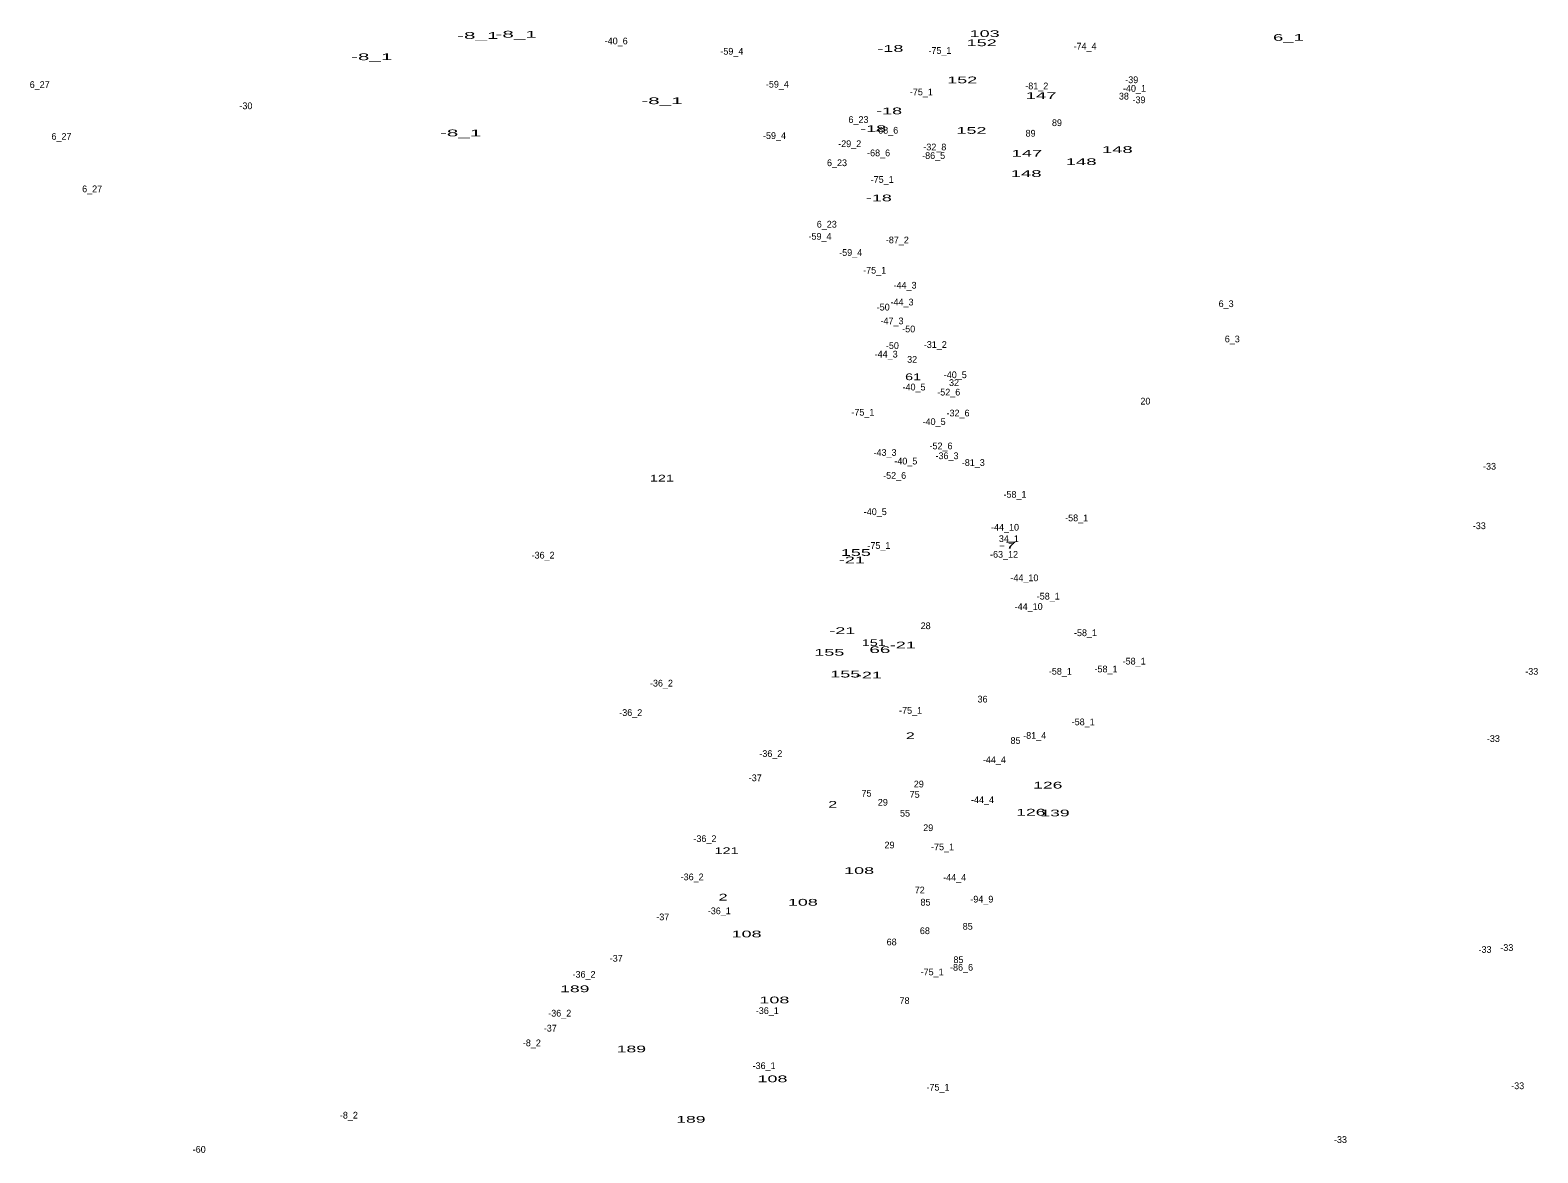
# Model space of a CAD drawing. Extents: x -659624 to -656248, y -1006345 to -1003555.
# Drawn here: x -658623 to -657726, y -1005682 to -1005014 of the extents above; entities that cross this region are included whole.
import ezdxf
from ezdxf.enums import TextEntityAlignment as Align

# ---------------------------------------------------------------- set-up
doc = ezdxf.new("R2010")
doc.units = 0
doc.header["$LTSCALE"] = 1.6
doc.layers.add('24', color=7, linetype='Continuous')

msp = doc.modelspace()

# ---------------------------------------------------------------- texts
at = {"layer": '24'}
for s, width, p in [('-8_1', 2.3, (-658356.751, -1005019.29)), ('-8_1', 2.3, (-658333.941, -1005018.53)), ('103', 2, (-658055.354, -1005018.16)), ('-18', 2, (-658111.421, -1005027.01)), ('152', 2, (-658057.107, -1005023.62)), ('6_1', 2.05, (-657874.723, -1005020.45)), ('-8_1', 2.3, (-658419.801, -1005031.94)), ('152', 2, (-658068.707, -1005045.69)), ('147', 2.05, (-658021.768, -1005054.98)), ('-8_1', 2.3, (-658247.211, -1005058.1)), ('-18', 2, (-658112.181, -1005064.11)), ('-8_1', 2.3, (-658366.931, -1005077.22)), ('-18', 2, (-658121.631, -1005074.67)), ('152', 2, (-658063.197, -1005075.75)), ('147', 2.05, (-658030.228, -1005089.32)), ('148', 2.05, (-657976.473, -1005087.09)), ('148', 2.05, (-657997.963, -1005094.32)), ('148', 2.05, (-658030.673, -1005101.36)), ('-18', 2, (-658118.271, -1005115.86)), ('61', 1.6, (-658097.913, -1005222.23)), ('121', 1.6, (-658247.274, -1005282.51)), ('-7', 2.2, (-658041.779, -1005322.36)), ('-21', 2, (-658134.281, -1005331.12)), ('155', 2, (-658131.937, -1005326.72)), ('-21', 2, (-658139.981, -1005373.17)), ('155', 2, (-658147.717, -1005386.08)), ('151', 1.6, (-658121.274, -1005380.35)), ('66', 2.1, (-658117.661, -1005384.48)), ('-21', 2, (-658104.041, -1005381.73)), ('155', 2, (-658138.217, -1005399.02)), ('-21', 2, (-658124.191, -1005399.61)), ('2', 1.8, (-658099.571, -1005435.69)), ('126', 1.95, (-658017.813, -1005465.05)), ('2', 1.8, (-658145.701, -1005476.46)), ('126', 1.95, (-658027.893, -1005481.13)), ('139', 1.95, (-658013.553, -1005481.58)), ('121', 1.6, (-658208.824, -1005504.04)), ('108', 2, (-658130.014, -1005515.85)), ('2', 1.8, (-658210.871, -1005531.65)), ('108', 2, (-658163.464, -1005534.69)), ('108', 2, (-658196.914, -1005553.54)), ('189', 1.95, (-658299.063, -1005586.15)), ('108', 2, (-658180.384, -1005592.77)), ('189', 1.95, (-658265.403, -1005621.92)), ('108', 2, (-658181.534, -1005639.69)), ('189', 1.95, (-658230.033, -1005663.77))]:
    msp.add_text(s, height=4, dxfattribs=dict(at, width=width)).set_placement(p, align=Align.CENTER)
for s, p in [('-40_6', (-658274.456, -1005022.54)), ('-59_4', (-658205.662, -1005028.67)), ('-75_1', (-658081.942, -1005028.19)), ('-74_4', (-657995.636, -1005025.64)), ('-39', (-657967.9, -1005045.62)), ('6_27', (-658617.226, -1005048.46)), ('-59_4', (-658178.592, -1005048.26)), ('-75_1', (-658093.002, -1005052.85)), ('-81_2', (-658024.366, -1005049.28)), ('38', (-657972.557, -1005055.35)), ('-40_1', (-657966.274, -1005050.72)), ('-30', (-658494.619, -1005061.09)), ('-39', (-657963.58, -1005057.54)), ('6_23', (-658130.39, -1005069.28)), ('89', (-658012.373, -1005071.15)), ('6_27', (-658604.296, -1005079.28)), ('-59_4', (-658180.322, -1005078.8)), ('-68_6', (-658113.613, -1005075.63)), ('89', (-658028.043, -1005077.4)), ('-29_2', (-658135.598, -1005083.66)), ('-68_6', (-658118.413, -1005089.08)), ('-86_5', (-658085.688, -1005090.67)), ('-32_8', (-658084.982, -1005085.59)), ('6_23', (-658143.14, -1005094.96)), ('-75_1', (-658116.302, -1005104.89)), ('6_27', (-658586.036, -1005110.48)), ('6_23', (-658149.22, -1005131.49)), ('-59_4', (-658153.252, -1005138.71)), ('-87_2', (-658107.278, -1005140.85)), ('-59_4', (-658135.012, -1005148.32)), ('-75_1', (-658120.762, -1005158.86)), ('-44_3', (-658102.681, -1005167.78)), ('-50', (-658115.679, -1005180.8)), ('-44_3', (-658104.501, -1005177.8)), ('6_3', (-657911.771, -1005178.77)), ('-47_3', (-658110.462, -1005188.99)), ('-50', (-658100.509, -1005193.76)), ('-50', (-658110.209, -1005203.66)), ('-31_2', (-658084.696, -1005203.04)), ('6_3', (-657908.121, -1005199.73)), ('-44_3', (-658113.921, -1005208.76)), ('32', (-658098.477, -1005211.88)), ('-40_5', (-658072.831, -1005221.03)), ('32', (-658073.567, -1005225.66)), ('-40_5', (-658097.341, -1005228.34)), ('-52_6', (-658076.708, -1005231.34)), ('-75_1', (-658127.752, -1005243.32)), ('-32_6', (-658071.168, -1005243.77)), ('20', (-657959.771, -1005236.7)), ('-40_5', (-658085.411, -1005248.9)), ('-43_3', (-658114.587, -1005267.23)), ('-52_6', (-658081.318, -1005263.32)), ('-36_3', (-658077.748, -1005269.19)), ('-40_5', (-658102.231, -1005272.36)), ('-81_3', (-658062.116, -1005273.21)), ('-33', (-657755.155, -1005275.42)), ('-52_6', (-658108.868, -1005280.89)), ('-58_1', (-658037.336, -1005292.14)), ('-40_5', (-658120.401, -1005302.46)), ('-58_1', (-658000.656, -1005306.12)), ('-44_10', (-658043.249, -1005311.71)), ('-33', (-657761.245, -1005310.81)), ('-75_1', (-658118.232, -1005322.54)), ('34_1', (-658040.943, -1005318.47)), ('-36_2', (-658317.908, -1005328.3)), ('-63_12', (-658043.822, -1005327.82)), ('-44_10', (-658031.709, -1005341.77)), ('-44_10', (-658029.189, -1005358.84)), ('-58_1', (-658017.536, -1005352.68)), ('28', (-658090.427, -1005370.28)), ('-58_1', (-657995.416, -1005374.43)), ('-58_1', (-657983.186, -1005395.98)), ('-58_1', (-657966.486, -1005391.32)), ('-36_2', (-658247.538, -1005404.4)), ('-58_1', (-658010.356, -1005397.34)), ('-33', (-657730.055, -1005397.38)), ('36', (-658056.613, -1005413.89)), ('-36_2', (-658265.798, -1005421.9)), ('-75_1', (-658099.402, -1005420.61)), ('-58_1', (-657996.766, -1005427.44)), ('85', (-658036.997, -1005438.52)), ('-81_4', (-658025.58, -1005435.5)), ('-33', (-657752.875, -1005437.34)), ('-36_2', (-658182.498, -1005446.26)), ('-44_4', (-658049.526, -1005449.89)), ('-37', (-658191.761, -1005460.7)), ('29', (-658094.513, -1005464.4)), ('75', (-658125.603, -1005469.88)), ('29', (-658115.903, -1005475.24)), ('75', (-658096.973, -1005470.55)), ('-44_4', (-658056.636, -1005473.74)), ('55', (-658102.697, -1005481.74)), ('29', (-658088.903, -1005490.37)), ('-36_2', (-658221.678, -1005496.86)), ('29', (-658111.913, -1005500.64)), ('-75_1', (-658080.392, -1005501.76)), ('-36_2', (-658229.278, -1005519.6)), ('-44_4', (-658073.176, -1005519.89)), ('72', (-658093.953, -1005527.37)), ('-36_1', (-658213.132, -1005539.78)), ('85', (-658090.527, -1005534.65)), ('-94_9', (-658057.048, -1005532.85)), ('-37', (-658246.741, -1005543.39)), ('85', (-658065.417, -1005549.01)), ('68', (-658090.893, -1005551.62)), ('68', (-658110.663, -1005558.28)), ('-33', (-657757.825, -1005562.76)), ('-33', (-657744.885, -1005561.62)), ('-37', (-658274.431, -1005568.01)), ('-86_6', (-658069.093, -1005573.38)), ('85', (-658070.937, -1005568.85)), ('-36_2', (-658293.568, -1005577.53)), ('-75_1', (-658086.602, -1005576.13)), ('78', (-658102.983, -1005593.17)), ('-36_2', (-658308.018, -1005600.64)), ('-36_1', (-658184.602, -1005599.13)), ('-37', (-658313.641, -1005609.55)), ('-8_2', (-658324.583, -1005618.3)), ('-36_1', (-658186.502, -1005631.86)), ('-75_1', (-658083.102, -1005644.67)), ('-33', (-657738.425, -1005643.81)), ('-8_2', (-658433.373, -1005661.3)), ('-60', (-658522.394, -1005681.63)), ('-33', (-657843.785, -1005675.77))]:
    msp.add_text(s, height=4, dxfattribs=at).set_placement(p, align=Align.CENTER)

doc.saveas('drawing.dxf')
